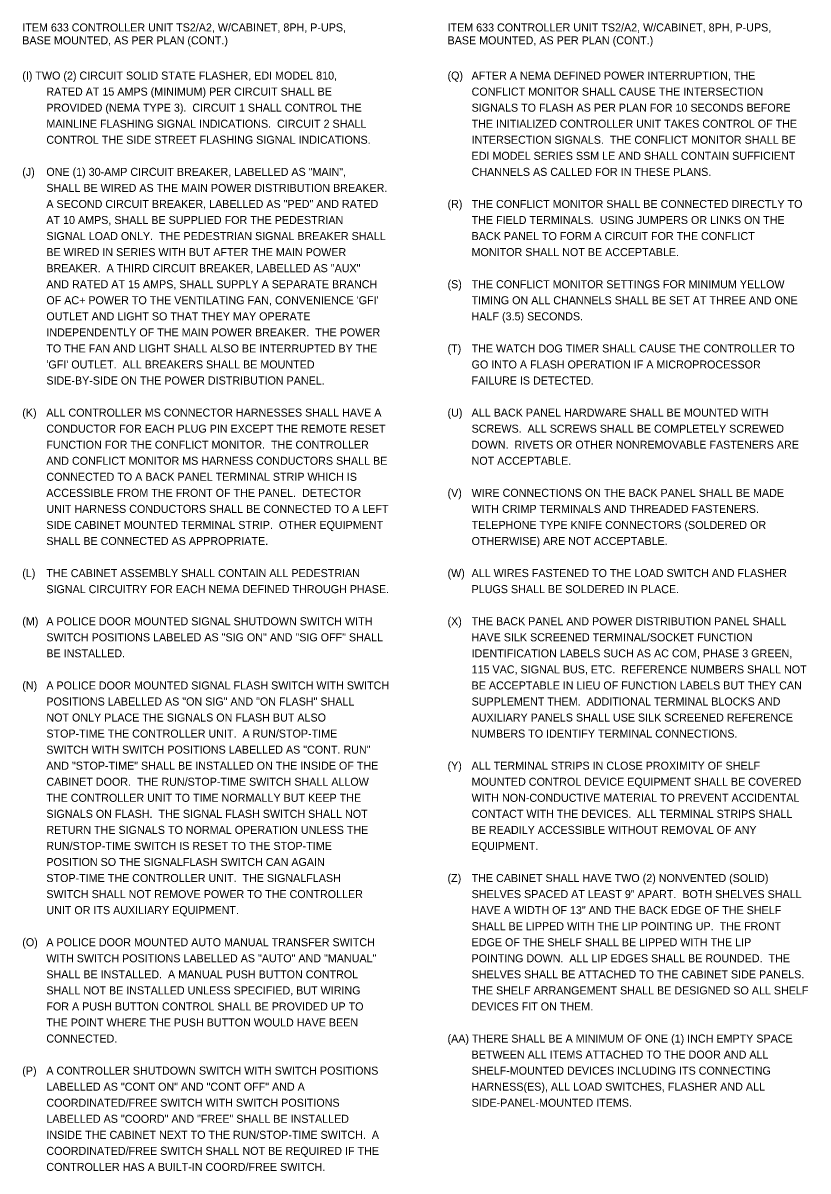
# Model space of a CAD drawing. Extents: x -27 to 74, y -37 to 38.
# Drawn here: x 2.41 to 16.1, y 17.63 to 37.66 of the extents above; entities that cross this region are included whole.
import ezdxf

# ---------------------------------------------------------------- set-up
doc = ezdxf.new("R2010")
doc.units = 0
doc.layers.add('SH_Data', color=7, linetype='Continuous')

msp = doc.modelspace()

# ---------------------------------------------------------------- texts
at = {"layer": 'SH_Data'}
for s, p in [('ITEM 633 CONTROLLER UNIT TS2/A2, W/CABINET, 8PH, P-UPS, ', (2.394, 37.51)), ('ITEM 633 CONTROLLER UNIT TS2/A2, W/CABINET, 8PH, P-UPS, ', (9.814, 37.51)), ('BASE MOUNTED, AS PER PLAN (CONT.)', (2.394, 37.285)), ('BASE MOUNTED, AS PER PLAN (CONT.)', (9.814, 37.285)), ('(I) TWO (2) CIRCUIT SOLID STATE FLASHER, EDI MODEL 810, ', (2.394, 36.67)), ('(Q)', (9.814, 36.67)), ('AFTER A NEMA DEFINED POWER INTERRUPTION, THE ', (10.234, 36.67)), ('RATED AT 15 AMPS (MINIMUM) PER CIRCUIT SHALL BE ', (2.814, 36.39)), ('CONFLICT MONITOR SHALL CAUSE THE INTERSECTION ', (10.234, 36.39)), ('PROVIDED (NEMA TYPE 3).  CIRCUIT 1 SHALL CONTROL THE ', (2.814, 36.11)), ('SIGNALS TO FLASH AS PER PLAN FOR 10 SECONDS BEFORE ', (10.234, 36.11)), ('MAINLINE FLASHING SIGNAL INDICATIONS.  CIRCUIT 2 SHALL ', (2.814, 35.83)), ('THE INITIALIZED CONTROLLER UNIT TAKES CONTROL OF THE ', (10.234, 35.83)), ('CONTROL THE SIDE STREET FLASHING SIGNAL INDICATIONS.', (2.814, 35.55)), ('INTERSECTION SIGNALS.  THE CONFLICT MONITOR SHALL BE ', (10.234, 35.55)), ('EDI MODEL SERIES SSM LE AND SHALL CONTAIN SUFFICIENT ', (10.234, 35.27)), ('(J)', (2.394, 34.99)), ('ONE (1) 30-AMP CIRCUIT BREAKER, LABELLED AS "MAIN", ', (2.814, 34.99)), ('CHANNELS AS CALLED FOR IN THESE PLANS.', (10.234, 34.99)), ('SHALL BE WIRED AS THE MAIN POWER DISTRIBUTION BREAKER.  ', (2.814, 34.71)), ('A SECOND CIRCUIT BREAKER, LABELLED AS "PED" AND RATED ', (2.814, 34.43)), ('(R)', (9.814, 34.43)), ('THE CONFLICT MONITOR SHALL BE CONNECTED DIRECTLY TO ', (10.234, 34.43)), ('AT 10 AMPS, SHALL BE SUPPLIED FOR THE PEDESTRIAN ', (2.814, 34.15)), ('THE FIELD TERMINALS.  USING JUMPERS OR LINKS ON THE ', (10.234, 34.15)), ('SIGNAL LOAD ONLY.  THE PEDESTRIAN SIGNAL BREAKER SHALL ', (2.814, 33.87)), ('BACK PANEL TO FORM A CIRCUIT FOR THE CONFLICT ', (10.234, 33.87)), ('BE WIRED IN SERIES WITH BUT AFTER THE MAIN POWER ', (2.814, 33.59)), ('MONITOR SHALL NOT BE ACCEPTABLE.', (10.234, 33.59)), ('BREAKER.  A THIRD CIRCUIT BREAKER, LABELLED AS "AUX" ', (2.814, 33.31)), ('AND RATED AT 15 AMPS, SHALL SUPPLY A SEPARATE BRANCH ', (2.814, 33.03)), ('(S)', (9.814, 33.03)), ('THE CONFLICT MONITOR SETTINGS FOR MINIMUM YELLOW ', (10.234, 33.03)), ("OF AC+ POWER TO THE VENTILATING FAN, CONVENIENCE 'GFI' ", (2.814, 32.75)), ('TIMING ON ALL CHANNELS SHALL BE SET AT THREE AND ONE ', (10.234, 32.75)), ('OUTLET AND LIGHT SO THAT THEY MAY OPERATE ', (2.814, 32.47)), ('HALF (3.5) SECONDS.', (10.234, 32.47)), ('INDEPENDENTLY OF THE MAIN POWER BREAKER.  THE POWER ', (2.814, 32.19)), ('TO THE FAN AND LIGHT SHALL ALSO BE INTERRUPTED BY THE ', (2.814, 31.91)), ('(T)', (9.814, 31.91)), ('THE WATCH DOG TIMER SHALL CAUSE THE CONTROLLER TO ', (10.234, 31.91)), ("'GFI' OUTLET.  ALL BREAKERS SHALL BE MOUNTED ", (2.814, 31.63)), ('GO INTO A FLASH OPERATION IF A MICROPROCESSOR ', (10.234, 31.63)), ('SIDE-BY-SIDE ON THE POWER DISTRIBUTION PANEL.', (2.814, 31.35)), ('FAILURE IS DETECTED.', (10.234, 31.35)), ('(K)', (2.394, 30.79)), ('ALL CONTROLLER MS CONNECTOR HARNESSES SHALL HAVE A ', (2.814, 30.79)), ('(U)', (9.814, 30.79)), ('ALL BACK PANEL HARDWARE SHALL BE MOUNTED WITH ', (10.234, 30.79)), ('CONDUCTOR FOR EACH PLUG PIN EXCEPT THE REMOTE RESET ', (2.814, 30.51)), ('SCREWS.  ALL SCREWS SHALL BE COMPLETELY SCREWED ', (10.234, 30.51)), ('FUNCTION FOR THE CONFLICT MONITOR.  THE CONTROLLER ', (2.814, 30.23)), ('DOWN.  RIVETS OR OTHER NONREMOVABLE FASTENERS ARE ', (10.234, 30.23)), ('AND CONFLICT MONITOR MS HARNESS CONDUCTORS SHALL BE ', (2.814, 29.95)), ('NOT ACCEPTABLE.', (10.234, 29.95)), ('CONNECTED TO A BACK PANEL TERMINAL STRIP WHICH IS ', (2.814, 29.67)), ('ACCESSIBLE FROM THE FRONT OF THE PANEL.  DETECTOR ', (2.814, 29.39)), ('(V)', (9.814, 29.39)), ('WIRE CONNECTIONS ON THE BACK PANEL SHALL BE MADE ', (10.234, 29.39)), ('UNIT HARNESS CONDUCTORS SHALL BE CONNECTED TO A LEFT ', (2.814, 29.11)), ('WITH CRIMP TERMINALS AND THREADED FASTENERS.  ', (10.234, 29.11)), ('SIDE CABINET MOUNTED TERMINAL STRIP.  OTHER EQUIPMENT ', (2.814, 28.83)), ('TELEPHONE TYPE KNIFE CONNECTORS (SOLDERED OR ', (10.234, 28.83)), ('SHALL BE CONNECTED AS APPROPRIATE.', (2.814, 28.55)), ('OTHERWISE) ARE NOT ACCEPTABLE.', (10.234, 28.55)), ('(L)', (2.394, 27.99)), ('THE CABINET ASSEMBLY SHALL CONTAIN ALL PEDESTRIAN ', (2.814, 27.99)), ('(W)', (9.814, 27.99)), ('ALL WIRES FASTENED TO THE LOAD SWITCH AND FLASHER ', (10.234, 27.99)), ('SIGNAL CIRCUITRY FOR EACH NEMA DEFINED THROUGH PHASE.', (2.814, 27.71)), ('PLUGS SHALL BE SOLDERED IN PLACE.', (10.234, 27.71)), ('(M)', (2.394, 27.15)), ('A POLICE DOOR MOUNTED SIGNAL SHUTDOWN SWITCH WITH ', (2.814, 27.15)), ('(X)', (9.814, 27.15)), ('THE BACK PANEL AND POWER DISTRIBUTION PANEL SHALL ', (10.234, 27.15)), ('SWITCH POSITIONS LABELED AS "SIG ON" AND "SIG OFF" SHALL ', (2.814, 26.87)), ('HAVE SILK SCREENED TERMINAL/SOCKET FUNCTION ', (10.234, 26.87)), ('BE INSTALLED.', (2.814, 26.59)), ('IDENTIFICATION LABELS SUCH AS AC COM, PHASE 3 GREEN, ', (10.234, 26.59)), ('115 VAC, SIGNAL BUS, ETC.  REFERENCE NUMBERS SHALL NOT ', (10.234, 26.31)), ('(N)', (2.394, 26.03)), ('A POLICE DOOR MOUNTED SIGNAL FLASH SWITCH WITH SWITCH ', (2.814, 26.03)), ('BE ACCEPTABLE IN LIEU OF FUNCTION LABELS BUT THEY CAN ', (10.234, 26.03)), ('POSITIONS LABELLED AS "ON SIG" AND "ON FLASH" SHALL ', (2.814, 25.75)), ('SUPPLEMENT THEM.  ADDITIONAL TERMINAL BLOCKS AND ', (10.234, 25.75)), ('NOT ONLY PLACE THE SIGNALS ON FLASH BUT ALSO ', (2.814, 25.47)), ('AUXILIARY PANELS SHALL USE SILK SCREENED REFERENCE ', (10.234, 25.47)), ('STOP-TIME THE CONTROLLER UNIT.  A RUN/STOP-TIME ', (2.814, 25.19)), ('NUMBERS TO IDENTIFY TERMINAL CONNECTIONS.', (10.234, 25.19)), ('SWITCH WITH SWITCH POSITIONS LABELLED AS "CONT. RUN" ', (2.814, 24.91)), ('AND "STOP-TIME" SHALL BE INSTALLED ON THE INSIDE OF THE ', (2.814, 24.63)), ('(Y)', (9.814, 24.63)), ('ALL TERMINAL STRIPS IN CLOSE PROXIMITY OF SHELF ', (10.234, 24.63)), ('CABINET DOOR.  THE RUN/STOP-TIME SWITCH SHALL ALLOW ', (2.814, 24.35)), ('MOUNTED CONTROL DEVICE EQUIPMENT SHALL BE COVERED ', (10.234, 24.35)), ('THE CONTROLLER UNIT TO TIME NORMALLY BUT KEEP THE ', (2.814, 24.07)), ('WITH NON-CONDUCTIVE MATERIAL TO PREVENT ACCIDENTAL ', (10.234, 24.07)), ('SIGNALS ON FLASH.  THE SIGNAL FLASH SWITCH SHALL NOT ', (2.814, 23.79)), ('CONTACT WITH THE DEVICES.  ALL TERMINAL STRIPS SHALL ', (10.234, 23.79)), ('RETURN THE SIGNALS TO NORMAL OPERATION UNLESS THE ', (2.814, 23.51)), ('BE READILY ACCESSIBLE WITHOUT REMOVAL OF ANY ', (10.234, 23.51)), ('RUN/STOP-TIME SWITCH IS RESET TO THE STOP-TIME ', (2.814, 23.23)), ('EQUIPMENT.', (10.234, 23.23)), ('POSITION SO THE SIGNALFLASH SWITCH CAN AGAIN ', (2.814, 22.95)), ('STOP-TIME THE CONTROLLER UNIT.  THE SIGNALFLASH ', (2.814, 22.67)), ('(Z)', (9.814, 22.67)), ('THE CABINET SHALL HAVE TWO (2) NONVENTED (SOLID) ', (10.234, 22.67)), ('SWITCH SHALL NOT REMOVE POWER TO THE CONTROLLER ', (2.814, 22.39)), ('SHELVES SPACED AT LEAST 9" APART.  BOTH SHELVES SHALL ', (10.234, 22.39)), ('UNIT OR ITS AUXILIARY EQUIPMENT.', (2.814, 22.11)), ('HAVE A WIDTH OF 13" AND THE BACK EDGE OF THE SHELF ', (10.234, 22.11)), ('SHALL BE LIPPED WITH THE LIP POINTING UP.  THE FRONT ', (10.234, 21.83)), ('(O)', (2.394, 21.55)), ('A POLICE DOOR MOUNTED AUTO MANUAL TRANSFER SWITCH ', (2.814, 21.55)), ('EDGE OF THE SHELF SHALL BE LIPPED WITH THE LIP ', (10.234, 21.55)), ('WITH SWITCH POSITIONS LABELLED AS "AUTO" AND "MANUAL" ', (2.814, 21.27)), ('POINTING DOWN.  ALL LIP EDGES SHALL BE ROUNDED.  THE ', (10.234, 21.27)), ('SHALL BE INSTALLED.  A MANUAL PUSH BUTTON CONTROL ', (2.814, 20.99)), ('SHELVES SHALL BE ATTACHED TO THE CABINET SIDE PANELS.  ', (10.234, 20.99)), ('SHALL NOT BE INSTALLED UNLESS SPECIFIED, BUT WIRING ', (2.814, 20.71)), ('THE SHELF ARRANGEMENT SHALL BE DESIGNED SO ALL SHELF ', (10.234, 20.71)), ('FOR A PUSH BUTTON CONTROL SHALL BE PROVIDED UP TO ', (2.814, 20.43)), ('DEVICES FIT ON THEM.', (10.234, 20.43)), ('THE POINT WHERE THE PUSH BUTTON WOULD HAVE BEEN ', (2.814, 20.15)), ('CONNECTED.', (2.814, 19.87)), ('(AA) THERE SHALL BE A MINIMUM OF ONE (1) INCH EMPTY SPACE ', (9.814, 19.87)), ('BETWEEN ALL ITEMS ATTACHED TO THE DOOR AND ALL ', (10.234, 19.59)), ('(P)', (2.394, 19.31)), ('A CONTROLLER SHUTDOWN SWITCH WITH SWITCH POSITIONS ', (2.814, 19.31)), ('SHELF-MOUNTED DEVICES INCLUDING ITS CONNECTING ', (10.234, 19.31)), ('LABELLED AS "CONT ON" AND "CONT OFF" AND A ', (2.814, 19.03)), ('HARNESS(ES), ALL LOAD SWITCHES, FLASHER AND ALL ', (10.234, 19.03)), ('COORDINATED/FREE SWITCH WITH SWITCH POSITIONS ', (2.814, 18.75)), ('SIDE-PANEL-MOUNTED ITEMS.', (10.234, 18.75)), ('LABELLED AS "COORD" AND "FREE" SHALL BE INSTALLED ', (2.814, 18.47)), ('INSIDE THE CABINET NEXT TO THE RUN/STOP-TIME SWITCH.  A ', (2.814, 18.19)), ('COORDINATED/FREE SWITCH SHALL NOT BE REQUIRED IF THE ', (2.814, 17.91)), ('CONTROLLER HAS A BUILT-IN COORD/FREE SWITCH.', (2.814, 17.63))]:
    msp.add_text(s, height=0.14, dxfattribs=at).set_placement(p)

doc.saveas('drawing.dxf')
